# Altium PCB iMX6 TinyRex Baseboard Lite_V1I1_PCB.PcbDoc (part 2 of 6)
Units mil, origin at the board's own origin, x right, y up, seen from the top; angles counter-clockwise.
Board outline 3149.61 x 3543.31 mil, 6 copper layers (L1, L2, L3, L4 (PWR), L5, L6), stack 60.634 mil thick; 385 components, 309 nets, 1566 pads, 914 vias.
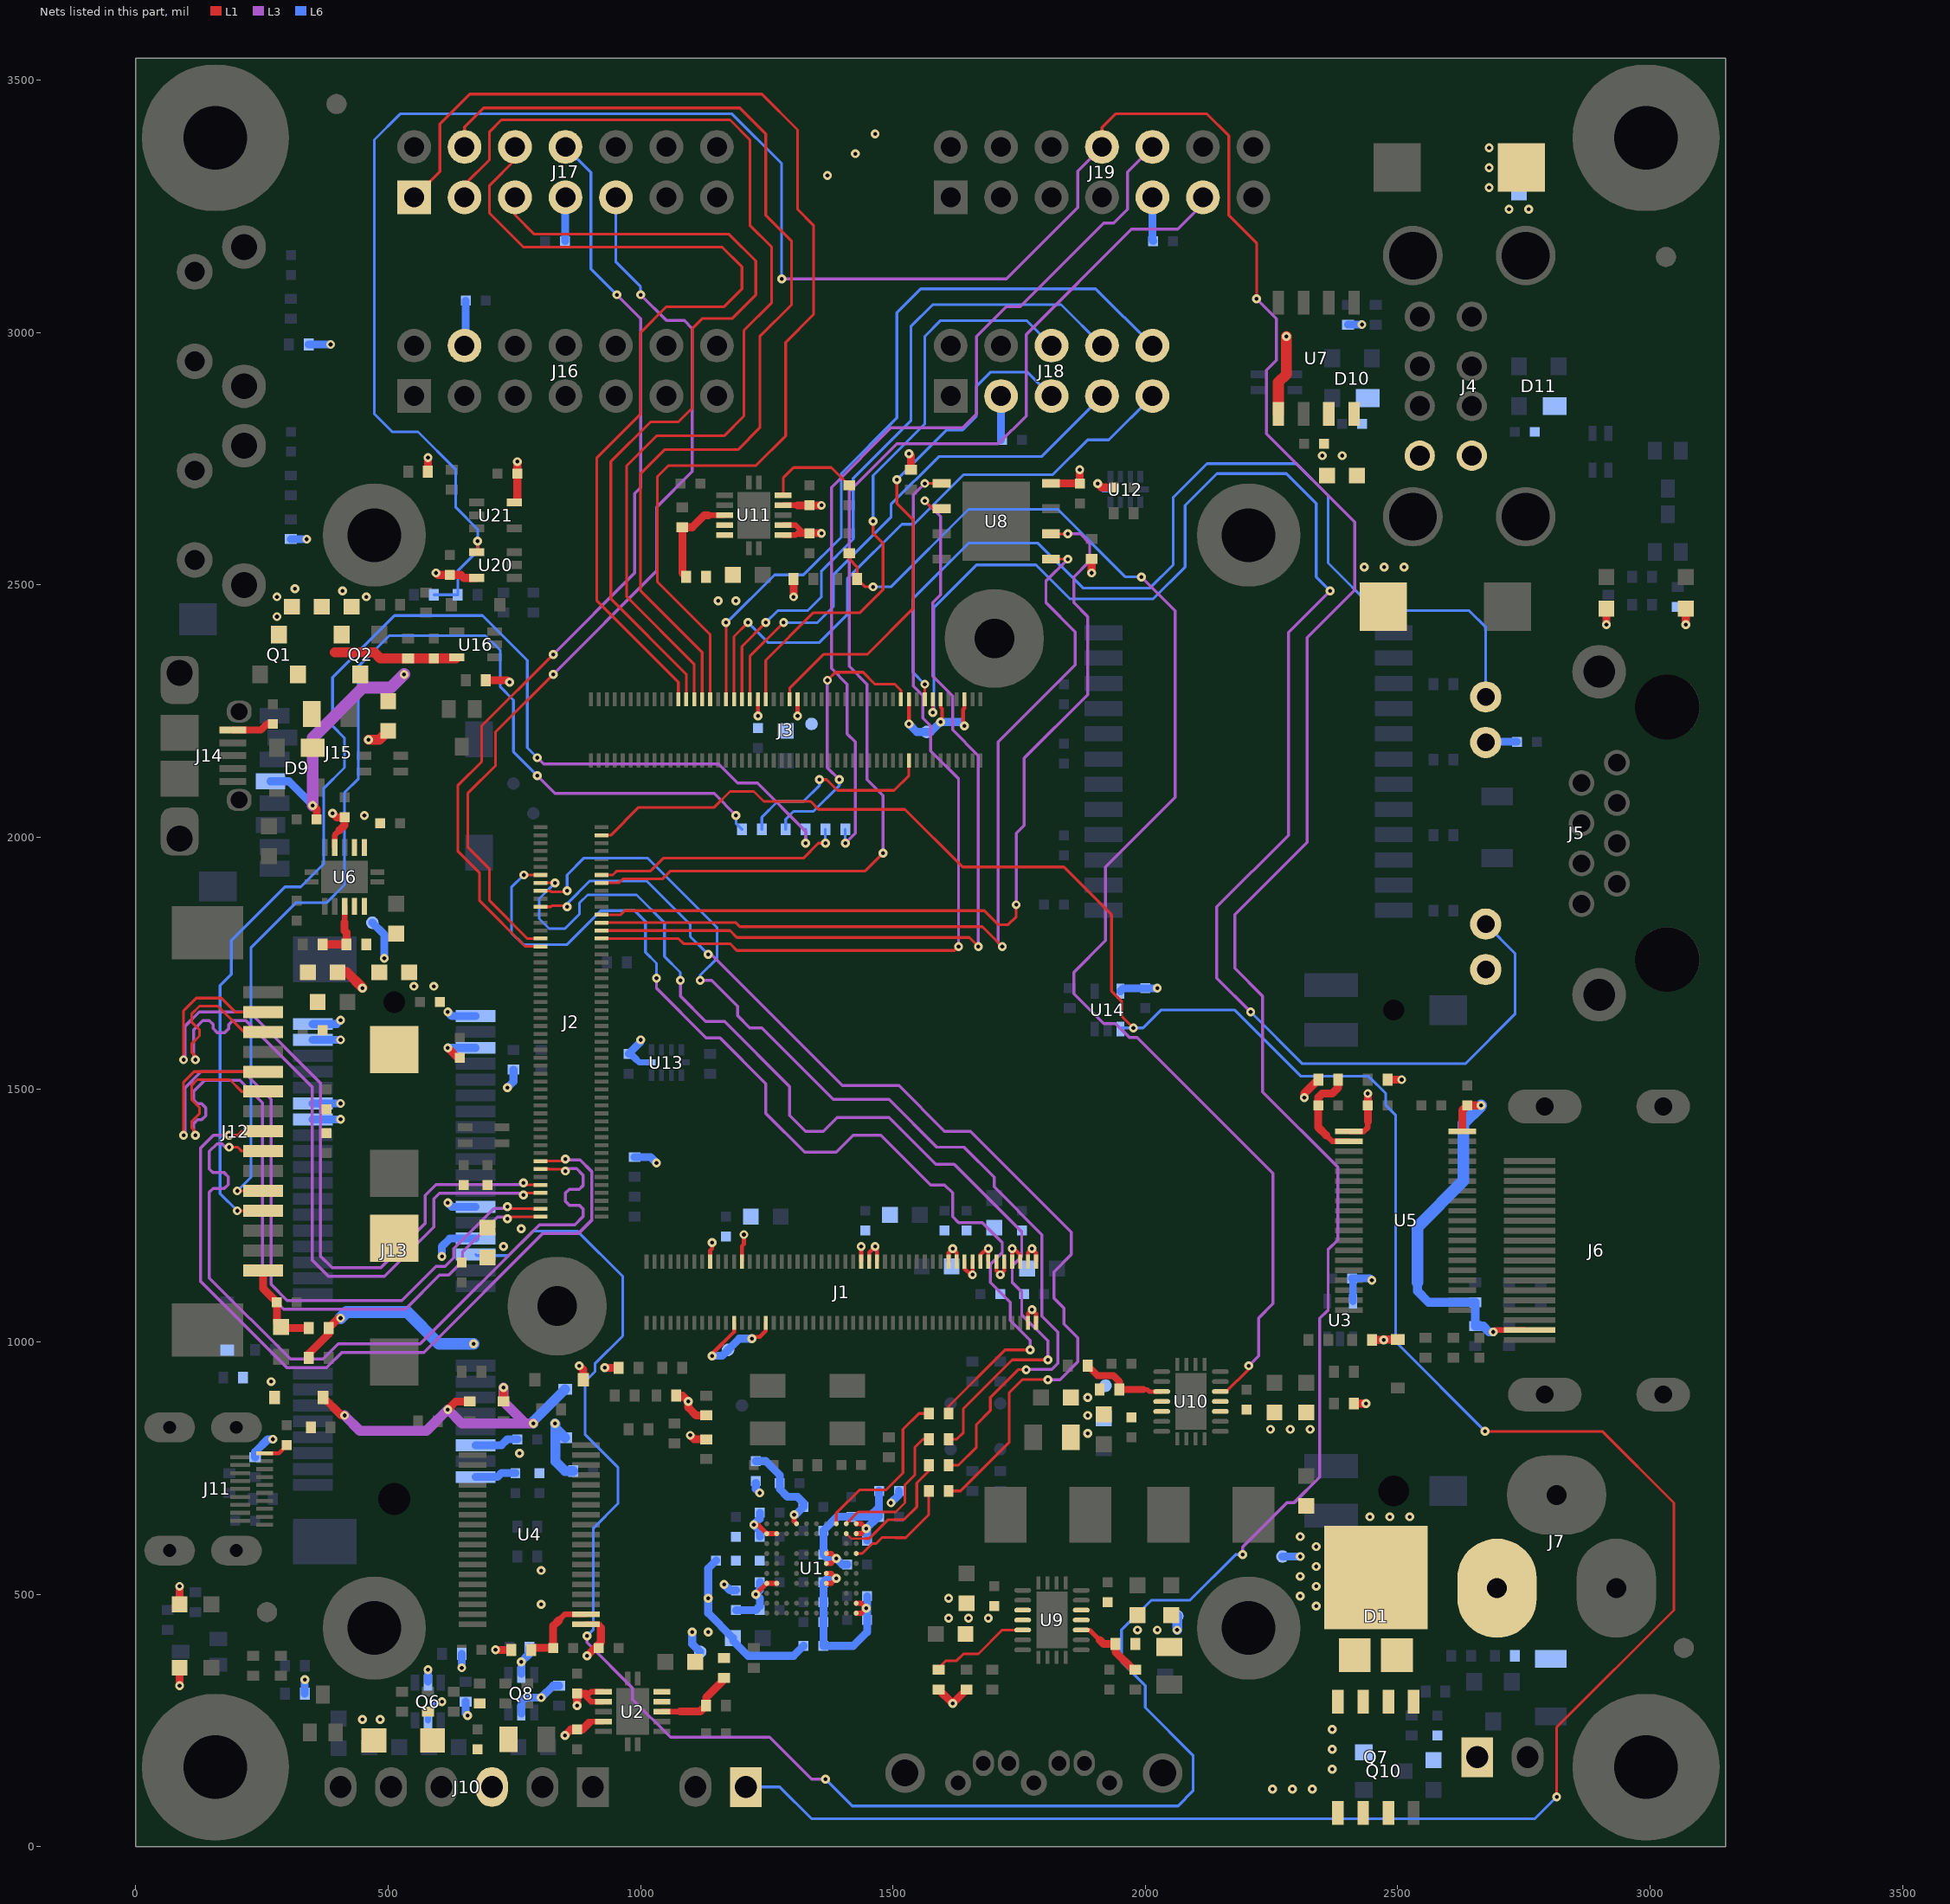
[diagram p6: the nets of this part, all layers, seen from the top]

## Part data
C1 C2 C3 C16 C29 C30 C37 C38 C61 C62 C63 C65 C66 C70 C231 C232 C381: library part C1608X5R0J226M080AC, "CAP CER 22UF 6.3V 20% X5R 0603"
C4 C5 C6 C7 C8 C9 C12 C13 C14 C15 C22 C23 C24 C25 C26 C27 C28 C32 C33 C34 C35 C36 C41 C42 C43 C44 C52 C53 C54 C55 C64 C69 C71 C72 C73 C74 C75 C76 C77 C79 C108 C114 C115 C116 C117 C118 C158 C160 C161 C165 C171 C176 C177 C187 C188 C190 C198 C200 C203 C230 C259 C260 C261 C265 C266 C267 C268: library part C1005X5R1H104K, "CAP CER .10UF 50V X5R 10% 0402"
C10 C20 C31 C58 C60 C91 C185: library part C1608X5R0J106M, "CAP CER 10UF 6.3V X5R 20% 0603"
C11 C17: library part JMK212BJ476MG-T, "CAP CER 47UF 6.3V 20% X5R 0805"
C18 C56 C89: library part C1005X5R1C105K, "CAP CER 1.0UF 16V X5R 0402"
C19 C57 C90 C262 C263 C264: library part C1005X5R1A475M, "CAP CER 4.7UF 10V 20% X5R 0402"
C21 C59 C92: library part GRM155R71H272KA01D, "CAP CER 2700PF 50V 10% X7R 0402"
C39 C40 C67 C68: library part C1005X5R1A225K, "CAP CER 2.2UF 10V 10% X5R 0402"
C45 C46 C47 C50 C51 C183 C184: library part C1005X7R1H221K, "CAP CER 220PF 50V X7R 10% 0402"
C48 C49: library part C1005C0G1H150J, "CAP CER 15PF 50V 5% NP0 0402"
C78: library part C2012X5R1C106M, "CAP CER 10UF 16V 20% X5R 0805"
C106: library part C2012X5R1C226K, "CAP CER 22UF 16V 10% X5R 0805"
C119: library part C1206X102KGRACTU, "CAP CER 1000PF 2000V X7R 1206 FT"
C156 C159: library part T495D337K010ATE150, "CAP TANT 330UF 10V 10% 2917"
C257 C258: library part T520D337M006ATE045, "CAP TANT 330UF 6.3V 20% 2917"
CR1: library part Card_Mini_PCIe, "Card MIni PCIe"
CR2: library part Card_Micro_SD, "Card Micro SD"
D1: "DIODE SCHOTTKY 40V 10A TO277A"
D2 D3 D6 D7 D16: "DIODE SCHOTTKY 30V 0.2A SOD323"
D4 D8 D12 D13 D19: "SUPPRESSOR ESD 24VDC 0603 SMD"
D5 D17 D18: library part "LS L29K-H1J2-1-Z", "LED SMARTLED RED 630NM 0603 SMD"
D9 D10 D11: "DIODE SWITCHING 50V SOT-143"
D14: library part "LG L29K-G2J1-24-Z", "LED SMARTLED GREEN 570NM 0603"
D15: "DIODE SCHOTTKY 40V 1A SOD123L"
D27: "DIODE SCHTKY 30MA 30V SOD-323"
FB1 FB2 FB24: library part MPZ1608S601A, "FERRITE CHIP BEAD 600 OHM SMD 1A"
FB3 FB4 FB5 FB8 FB11: "FERRITE CHIP 600 OHM 0402 420mA"
FB6 FB7 FB9 FB10 FB12: library part BLM18SG221TN1D, "FERRITE CHIP 220 OHM 2500MA 0603"
FID1 FID2 FID3 FID4 FID5 FID6 FID7 FID8: "Fiducial 40mil Diameter, 120mil Mask"
J1 J2 J3: library part DF40C-100DS-0.4V(51)_v1.1, "CONN RCPT 100POS 0.4MM SMD GOLD"
J4: library part 5787617-1_v1.1, "CONN RCPT R/A 4OVER4POS GOLD PCB"
J5: "CONN MOD JACK 8POS R/A G-Y PCB"
J6: library part 47151-0001_v1.1, "CONN RCPT 19POS HDMI RT ANG SMD"
J7: library part PJ-002AH_v1.1, "CONN PWR JACK 2.1X5.5MM HIGH CUR"
J8: "CONN HEADER 2POS .100 VERT GOLD"
J9: "CONN SATA HDR 7POS PCB VERT"
J10: library part 68001-206HLF, "CONN HEADER 6POS .100 STR 15AU"
J11: "CONN RCPT HDMI MICRO TYPE-D R/A"
J12: "CONN FPC BOTTOM 15POS 1.00MM R/A"
J13: "CONN MINI EXPRESS CARD 52POS SMD"
J14: library part 0475890001, "CONN RCPT MICRO USB AB R/A SMD"
J15: "CONN MICRO SD 8 POS SMD"
J16 J17 J19: library part D2514-6002-AR, "CONN HEADER 14POS VERT 10GOLD"
J18: library part D2510-6002-AR, "CONN HEADER 10POS VERT 10GOLD"
J20: "CONN MINI EXPRESS CARD LATCH SMD"
JP1: library part 68001-202HLF, "BERGSTIK II .100\" SR STRAIGHT"
L1 L2: library part IHLP2020CZER1R5M11, "FIXED IND 1.5UH 7.5A 18.5 MOHM"
L3 L4 L5 L6: "CHOKE COMM MODE 90 OHM .4A SMD"
M1: library part 3D_iMX6_TINYREX_MODULE_V1I1, "3D Model"
MH1 MH2 MH3 MH4: "Mounting Hole 7.4mm Diameter, 3.2mm Drill"
MH5 MH6: "Mounting Hole 5mm Diameter, 2mm Drill"
MH9 MH10 MH11 MH12: "Mounting Hole 5.2mm Diameter, 2.7mm Drill"
NUT3 NUT4: library part PFP1166, "ROEBUCK - PFP1166 - FULL NUT A4 SS M2 (PK 100)"
Q1 Q2: "MOSFET P-CH 20V 3.6A SOT-23"
Q3 Q4 Q5 Q9 Q11: "MOSFET N-CH 60V 310MA SOT323"
Q6 Q8: "MOSFET 2N-CH 60V 0.3A 6TSSOP"
Q7: "MOSFET P-CH 30V 8.8A 8-SOIC"
Q10: "TRANS PNP 40V 0.2A SOT23"
R1 R2 R3 R4 R10 R11 R23 R24 R26 R27 R28 R32 R33 R37 R44 R45 R52 R53 R64 R65 R81 R117 R140 R147 R201 R204 R206 R224 R247 R293: library part RC0402FR-0710KL, "RES 10.0K OHM 1/16W 1% 0402 SMD"
R5 R8 R9 R14 R15 R16 R22 R30 R31 R34 R39 R41 R46 R58 R59 R60 R61 R62 R63 R104 R105 R109 R135 R136 R138 R139 R153 R155 R162 R163 R164 R165 R174 R220 R304: library part RC0402JR-070RL, "RES 0.0 OHM 1/16W 0402 SMD"
R6 R7 R17 R19: library part RMCF0402FT4K99, "RES TF 4.99K OHM 1% 1/16W 0402"
R12 R13 R36 R40 R48 R49: library part RC0402FR-0747KL, "RES 47.0K OHM 1/16W 1% 0402 SMD"
R18: library part CRCW04022K10FKED, "RES 2.10K OHM 1/16W 1% 0402 SMD"
R20 R83 R226: library part CRCW04022K40FKED, "RES 2.40K OHM 1/16W 1% 0402 SMD"
R21 R50: library part RC0402FR-0727KL, "RES 27.0K OHM 1/16W 1% 0402 SMD"
R25 R29 R38 R214: library part RMCF0402FT100K, "RES 100K OHM 1/16W 1% 0402 SMD"
R35 R42 R43 R166 R167 R168 R169: library part RC0402FR-0722RL, "RES 22.0 OHM 1/16W 1% 0402 SMD"
R47: library part RC0402FR-0715KL, "RES 15.0K OHM 1/16W 1% 0402 SMD"
R51 R67: library part RC0402FR-071KL, "RES 1.00K OHM 1/16W 1% 0402 SMD"
R54 R55 R56 R57 R70 R71: library part RC0402FR-073K3L, "RES 3.30K OHM 1/16W 1% 0402 SMD"
R66 R141 R149: library part RMCF0402FT33R0, "RES TF 33 OHM 1% 1/16W 0402"
R68 R69 R144 R145 R146 R148: library part RMCF0402FT240R, "RES TF 240 OHM 1% 0.0625W 0402"
R72: library part CRCW0402390KFKED, "RES 390K OHM 1/16W 1% 0402 SMD"
R82: library part RC0402FR-073KL, "RES 3K OHM 1/16W 1% 0402 SMD"
R84 R85 R86 R87: library part RC0402FR-0775RL, "RES 75.0 OHM 1/16W 1% 0402 SMD"
R100: library part RNCP1206FTD1K00, "RES SMD 1K OHM 1% 1/2W 1206"
R211 R216: library part CRCW04021M02FKED, "RES 1.02M OHM 1/16W 1% 0402 SMD"
R213: library part CRCW0402113KFKED, "RES 113K OHM 1/16W 1% 0402 SMD"
R217: library part CRCW0402182KFKED, "RES 182K OHM 1/16W 1% 0402 SMD"
R225: library part RC0402FR-075K1L, "RES 5.10K OHM 1/16W 1% 0402 SMD"
R292: library part CRCW040211K8FKED, "RES 11.8K OHM 1/16W 1% 0402 SMD"
R296: library part CRCW040210K5FKED, "RES 10.5K OHM 1/16W 1% 0402 SMD"
R301: library part CRCW0402470KFKED, "RES 470K OHM 1/16W 1% 0402 SMD"
SCR3 SCR4: library part "MPMS 002 0008 PH", "MACHINE SCREW PAN PHILLIPS M2"
SPA3 SPA4: library part "SPACER 2.5/4.5X1.5MM", "SPACER 2.5/4.5X1.5MM"
SW1 SW2: "SWITCH TACTILE SPST-NO 0.05A 12V"
T1: "MODULE SINGLE GIGABIT LAN 24SOIC"
TP1 TP2 TP3 TP4 TP5 TP6 TP7 TP8 TP9 TP10 TP11 TP12 TP13 TP14 TP15: "Test Point 25mil"
U1: "IC RCVR HDMI 165MHZ LP 76-CSBGA"
U2 U6 U11: "IC REG LDO ADJ 1.5A 10SON"
U3: "IC BUFFER SCHMIT TRIG SC705"
U4: "IC HDMI RCVR PORT PROT 38-TSSOP"
U5: "IC HDMI TX PORT P/I 38-TSSOP"
U7: "IC SW DISTRIBUTION 2CHAN 8SOIC"
U8: library part SST25VF016B-75-4I-QAF, "IC FLASH 16MBIT 75MHZ 8WSON"
U9 U10: "IC REG BUCK BST SYNC ADJ 14VSON"
U12 U13: "IC USB SWITCH DUAL 1X2 10-QFN"
U14 U20 U21: "SINGLE POSITIVE AND GATE SC-70"
U16: "IC BUFF CMOS LVL/SFTR N-I SOT353"
U27: "IC VREF SHUNT ADJ SOT23-3"
Y1: library part ABM3B-28.63636MHZ-10-1-U-T, "CRYSTAL 28.63636MHZ 10PF SMD"

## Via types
v1: diameter 17.72, hole 7.87, L1 to L6, 471 vias
v2: diameter 17.72, hole 7.87, L1 to L6, tented both sides, 442 vias
v3: diameter 17.72, hole 7.87, L1 to L6, tented top, 1 vias

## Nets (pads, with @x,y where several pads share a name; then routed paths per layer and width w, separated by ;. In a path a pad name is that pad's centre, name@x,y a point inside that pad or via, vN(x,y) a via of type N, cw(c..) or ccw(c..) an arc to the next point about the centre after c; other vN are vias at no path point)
+1V2_TP: J3.6 J3.12 J3.20 TP7.1 | length 279.5
  L1 w6.69: v2(1594.49,2228.35) 1597.44,2231.3 1597.44,2254.16 1594.49,2257.11 J3.12@1594.49,2273.23
  L1 w7.87: v2(1531.5,2224.41) J3.20@1531.5,2273.23 ; v2(1641.73,2220.47) 1638.78,2223.43 1638.78,2252.95 1641.73,2255.9 J3.6@1641.73,2273.23
  L6 w15.75: v2(1531.5,2224.41) 1547.24,2208.66 TP7.1@1566.93,2208.66 1574.8,2208.66 v2(1594.49,2228.35) 1633.86,2228.35 v2(1641.73,2220.47)
+1V5: C20.1 FB10.2 R18.2 TP1.1 U6.9 U6.10 | length 80.7
  L6 w15.75: TP1.1@468.5,1830.71 492.13,1807.09 v1(492.13,1759.84)
+1V5_MPCIE: C259.1 C260.1 C261.1 C262.1 FB10.1 J13.6 J13.28 J13.48 | length 232.8
  L1 w15.75: v1(618.11,1582.68) 637.8,1562.99 C261.1@641.73,1562.99
  L6 w15.75: v1(618.11,1275.59) 625.98,1267.72 J13.28@673.23,1267.72 ; v1(618.11,1582.68) J13.48@673.23,1582.68 ; J13.6@673.23,795.28 724.41,795.28 736.22,807.09 C259.1@755.91,807.09
  other v1: 551.18,1704.72 590.55,1704.72
+1V8: C58.1 FB3.1 FB5.1 FB11.1 R82.2 TP4.1 U2.9 U2.10 | length 127.5
  L6 w15.75: v1(1102.36,425.2) 1102.36,401.57 TP4.1@1118.11,385.83 ; v1(1165.35,519.69) 1177.17,507.87 FB5.1@1188.98,507.87 ; FB11.1@1228.35,720.47 1228.35,708.66 v1(1236.22,700.79) ; v1(1496.06,681.1) 1511.81,696.85 FB3.1@1511.81,704.72
  other v1: 1133.86,425.2
+1V8_CVDD: C55.2 C177.2 FB5.2 U1.G1 U1.G2 | length 154.6
  L1 w9.84: v1(1228.35,500) U1.G1@1250,521.65 U1.G2@1269.69,521.65
  L6 w15.75: FB5.2@1188.98,468.5 1228.35,468.5 1236.22,476.38 1236.22,492.13 v1(1228.35,500) 1236.22,507.87 C177.2@1236.22,523.62
+1V8_DVDD: C41.2 C42.2 C43.2 C44.2 C45.1 C46.1 FB3.2 U1.A10 U1.B10 U1.D7 U1.E7 | length 438.5
  L1 w9.84: U1.E7@1368.11,561.02 1377.95,561.02 v1(1387.8,570.87) 1377.95,580.71 U1.D7@1368.11,580.71 ; U1.B10@1427.17,620.08 1437.01,620.08 v1(1446.85,629.92) 1437.01,639.76 U1.A10@1427.17,639.76
  L6 w15.75: C46.1@1409.45,559.06 1399.61,559.06 v1(1387.8,570.87) 1370.08,570.87 C43.2@1362.2,578.74 C42.2@1362.2,625.98 1389.76,653.54 C44.2@1417.32,653.54 1452.76,653.54 1472.44,673.23 ; C45.1@1448.82,606.3 1448.82,627.95 v1(1446.85,629.92) 1470.47,653.54 C41.2@1472.44,653.54 FB3.2@1472.44,704.72
+1V8_PVDD: C51.1 C190.2 FB11.2 U1.A4 | length 197.7
  L1 w9.84: v1(1304.13,657.48) 1304.13,644.68 U1.A4@1309.06,639.76
  L6 w15.75: FB11.2@1228.35,763.78 1248.03,763.78 1275.59,736.22 C190.2@1275.59,720.47 1275.59,708.66 1291.34,692.91 1311.02,692.91 1322.83,681.1 C51.1@1322.83,673.23 1307.09,657.48 v1(1304.13,657.48)
+2V5: C14.1 C91.1 C232.1 J3.48 J3.58 R224.2 R225.2 TP15.1 U11.9 U11.10 | length 101.6
  L1 w7.87: v2(1232.28,2240.16) J3.58@1232.28,2273.23 ; v2(1311.02,2240.16) J3.48@1311.02,2273.23
  L1 w15.75: v2(1303.15,2476.38) R224.2@1303.15,2511.81
  other v2: 1153.54,2468.5 1188.98,2468.5
+3V0_ALWAYS_TP: J1.69 J1.77 TP8.1 | length 226
  L1 w7.87: v2(1141.73,972.44) 1141.73,976.38 1185.04,1019.69 J1.77@1185.04,1037.8 ; v2(1220.47,1006.44) 1223.66,1009.63 1235.75,1009.63 1248.03,1021.91 J1.69@1248.03,1037.8
  L6 w15.75: v2(1141.73,972.44) 1161.42,972.44 TP8.1@1173.23,984.25 1195.42,1006.44 v2(1220.47,1006.44)
+3V3: C9.2 C12.1 C13.1 C17.1 C27.2 C28.2 C29.1 C30.1 C34.1 C35.1 C36.1 C68.1 C70.1 C75.2 C76.2 C115.1 C158.1 C171.1 C176.1 C185.1 C203.1 C231.1 D3.2 D5.2 D7.2 D14.2 D15.2 D17.2 D18.2 FB4.2 FB8.2 FB9.1 J1.22 J1.24 J1.42 J1.44 J1.46 J5.10 J5.12 J15.4 J16.4 J17.7 J18.3 J19.9 Q6.2 Q6.5 Q8.2 Q8.5 R6.2 R7.2 R10.2 R11.2 R12.2 R13.2 R32.2 R33.2 R36.2 R37.2 R46.2 R54.2 R56.2 R65.2 R70.2 R71.2 R81.2 R117.2 R138.1 R140.2 R147.2 R201.2 R204.1 R206.2 R216.2 TP13.1 U3.5 U8.8 U10.4 U10.5 U12.10 U13.10 U14.5 U20.5 U21.5 | length 3479.3
  L1 w7.87: J1.46@1437.01,1159.06 v2(1437.01,1188.98) ; J1.44@1452.76,1159.06 1452.76,1177.17 v2(1464.57,1188.98) 1468.5,1185.04 J1.42@1468.5,1159.06 ; J1.24@1610.24,1159.06 1610.24,1177.17 v2(1618.11,1185.04) 1625.98,1177.17 J1.22@1625.98,1159.06
  L1 w15.75: v1(86.61,318.9) D5.2@86.61,354.33 ; D14.2@86.61,480.31 v1(86.61,515.75) ; R37.2@342.52,968.5 342.52,976.38 381.89,1015.75 R138.1@381.89,1027.56 401.57,1047.24 v1(405.51,1047.24) ; v1(350.39,2062.99) 358.27,2055.12 C158.1@358.27,2035.43 ; R117.2@578.74,2724.41 v1(578.74,2751.97) ; v1(594.49,2523.62) 598.43,2519.69 C171.1@622.05,2519.69 643.7,2519.69 649.61,2513.78 U20.5@675.2,2513.78 U20.5@671.26,2513.78 ; R201.2@692.91,2311.02 736.22,2311.02 v1(740.16,2307.09) ; v1(712.6,389.76) R11.2@744.09,389.76 ; U21.5@750,2663.39 755.91,2669.29 v1(755.91,2744.09) ; v1(878.71,952.76) 886.58,944.88 D7.2@886.58,925.2 ; v1(929.13,948.82) R12.2@956.69,948.82 ; R13.2@1070.87,893.7 1082.68,893.7 v1(1094.49,881.89) 1094.49,870.08 1110.24,854.33 R6.2@1129.92,854.33 ; v1(1098.43,814.96) 1106.3,807.09 R7.2@1129.92,807.09 ; v1(1531.5,2759.84) 1535.43,2755.91 R206.2@1535.43,2728.35 ; U8.8@1812.99,2700.98 1869.88,2700.98 C203.1@1870.08,2700.79 v2(1870.08,2728.35) ; v1(1893.7,2523.62) R204.1@1893.7,2551.18 ; v2(1905.51,2700.79) 1913.39,2692.91 C9.2@1937.01,2692.91 ; v2(2314.96,1484.25) 2314.96,1492.13 R46.2@2342.52,1519.69 ; R36.2@2448.82,1003.94 v2(2472.44,1003.94) 2473.2,1004.69 D3.2@2500,1004.69 ; v1(2913.39,2421.26) D17.2@2913.39,2452.76 ; v1(3070.87,2421.26) D18.2@3070.87,2452.76
  L3 w23.62: v1(350.39,2062.99) 350.39,2196.85 449.8,2296.26 504.92,2296.26 v1(531.5,2322.83)
  L6 w11.81: Q6.2@578.74,250 578.74,267.72 596.06,285.04 603.94,285.04 v1(606.3,287.4) ; 992.13,1559.06 997.51,1553.67 U13.10@1017.32,1553.67 ; v2(1905.51,2700.79) 1917.32,2688.98 U12.10@1926.77,2688.98
  L6 w13.78: C75.2@976.38,1570.87 980.31,1570.87 992.13,1559.06
  L6 w14.96: C35.1@2409.45,1125.98 2411.42,1124.02 U3.5@2411.42,1080.71
  L6 w15.75: J15.4@266.73,2110.83 303.08,2110.83 350.39,2063.51 v1(350.39,2062.99) ; R147.2@307.09,2590.55 v1(338.58,2590.55) ; R81.2@334.65,303.15 v1(334.65,330.71) ; R140.2@342.52,2976.38 v1(385.83,2976.38) ; Q6.5@578.74,326.77 v1(578.74,350.39) ; v1(645.67,354.33) R70.2@645.67,381.89 ; J16.4@651.18,2974.02 653.54,2976.38 C36.1@653.54,3062.99 ; R56.2@653.54,287.4 653.54,263.78 v1(657.48,259.84) ; v2(736.22,1503.94) 748.03,1515.75 R65.2@748.03,1539.37 ; Q8.2@763.78,263.78 763.78,287.4 771.65,295.28 v1(803.15,295.28) 826.77,318.9 R54.2@838.58,318.9 ; Q8.5@763.78,342.52 v1(763.78,366.14) 779.53,381.89 R71.2@779.53,393.7 ; C28.2@850.39,3181.1 850.39,3266.14 J17.7@851.97,3267.72 ; C75.2@976.38,1570.87 1000,1594.49 v2(1000,1598.43) ; R10.2@988.19,1366.14 1019.69,1366.14 v2(1031.5,1354.33) ; FB8.2@1149.61,566.93 1133.86,551.18 v1(1133.86,492.13) 1133.86,462.6 C185.1@1183.07,413.39 1183.07,408 1213.12,377.95 1303.15,377.95 FB4.2@1322.83,397.64 ; C34.1@1714.17,2787.4 J18.3@1714.17,2874.02 ; U14.5@1950.79,1694.88 1956.69,1700.79 C76.2@2000,1700.79 v2(2023.62,1700.79) ; J19.9@2014.17,3267.72 2014.17,3182.68 C27.2@2015.75,3181.1 ; R32.2@2401.57,3015.75 v1(2429.13,3015.75) ; C35.1@2409.45,1125.98 2444.88,1125.98 v2(2448.82,1122.05) ; J5.10@2675.59,2188.98 C115.1@2736.22,2188.98
  L6 w23.62: v1(405.51,1047.24) 417.32,1059.06 537.58,1059.06 600.57,996.06 v1(669.29,996.06)
  other v1: 448.82,251.97 484.25,251.97 803.15,480.31 803.15,547.24 728.35,1188.98 763.78,1224.41
  other v2: 1885.83,818.9 1885.83,854.33 1885.83,889.76
+3V3_DVDDIO: C47.1 C50.1 C52.2 C53.2 C54.2 FB4.1 U1.F7 U1.G7 U1.J10 U1.K10 | length 420.4
  L1 w9.84: U1.G7@1368.11,521.65 1377.95,521.65 v1(1387.8,531.5) 1377.95,541.34 U1.F7@1368.11,541.34 ; U1.K10@1427.17,462.6 1437.01,462.6 v1(1446.85,472.44) 1437.01,482.28 U1.J10@1427.17,482.28
  L6 w15.75: v1(1387.8,531.5) 1370.08,531.5 C50.1@1362.2,523.62 C54.2@1362.2,444.88 FB4.1@1362.2,397.64 1421.26,397.64 1448.82,425.2 C52.2@1448.82,448.82 1448.82,470.47 v1(1446.85,472.44) 1448.82,474.41 C47.1@1448.82,496.06
+3V3_HDMI_IN: C72.1 R11.1 U4.2 | length 163
  L1 w11.02: 838.58,448.82 850.39,460.63 U4.2@891.73,460.63
  L1 w15.75: R11.1@783.46,389.76 787.4,393.7 C72.1@826.77,393.7 826.77,437.01 838.58,448.82
+3V3_HDMI_OUT: C23.1 R46.1 U5.2 | length 194.8
  L1 w11.02: 2358.27,1409.45 2370.08,1397.64 U5.2@2403.54,1397.64
  L1 w15.75: 2358.27,1409.45 2342.52,1425.2 C23.1@2342.52,1468.5 2342.52,1484.25 2350.39,1492.13 2370.08,1492.13 2381.89,1503.94 R46.1@2381.89,1519.69
+3V3_MPCIE: C257.1 C258.1 C263.1 C264.1 C265.1 C266.1 C267.1 C268.1 FB9.2 J13.2 J13.24 J13.39 J13.41 J13.52 | length 343.8
  L6 w15.75: J13.39@350.39,1440.95 v1(405.51,1440.95) ; J13.41@350.39,1472.44 v1(405.51,1472.44) ; v1(606.3,1169.29) 606.3,1188.98 622.05,1204.72 J13.24@673.23,1204.72 ; v1(618.11,1653.54) 625.98,1645.67 J13.52@673.23,1645.67 ; J13.2@673.23,732.28 716.54,732.28 724.41,740.16 C265.1@751.97,740.16
  other v1: 759.84,779.53
+3V3_TVDD: C183.1 C184.1 C187.2 C188.2 FB8.1 U1.B1 U1.B2 | length 109.6
  L1 w9.84: v1(1224.41,637.8) 1232.28,637.8 U1.B1@1250,620.08 U1.B2@1269.69,620.08
  L6 w15.75: C183.1@1236.22,614.17 1236.22,625.98 v1(1224.41,637.8) 1236.22,649.61 C184.1@1236.22,661.42
+5V: C11.1 C15.1 C16.1 C22.1 C40.1 C61.1 C62.1 C63.1 C71.1 C165.1 D6.2 FB1.1 FB2.1 FB6.1 FB7.1 FB24.1 J1.76 J1.84 R26.2 R104.1 R211.2 TP12.1 U4.1 U5.1 U7.7 U9.4 U9.5 | length 612.3
  L1 w7.87: J1.84@1137.8,1159.06 1137.8,1181.1 1141.73,1185.04 v2(1141.73,1196.85) ; J1.76@1200.79,1159.06 1200.79,1189.76 1204.72,1193.7 v2(1204.72,1212.6)
  L1 w11.02: U4.1@891.73,440.95 917.32,440.95 921.26,437.01 921.26,433.07 ; U5.1@2403.54,1417.32 2433.07,1417.32 2440.94,1425.2 2440.94,1437.01
  L1 w15.75: v1(893.7,377.95) 921.26,405.51 921.26,433.07 ; 2440.94,1437.01 C22.1@2440.94,1468.5 v2(2440.94,1492.13) ; R26.2@2480.31,1519.69 v2(2507.87,1519.69)
  L1 w19.68: FB7.1@399.61,1732.28 418.31,1732.28 v1@448.82,1701.77 ; v1(460.63,2192.91) 482.28,2192.91 FB24.1@500,2210.63
  L6 w19.68: v3(830.71,838.58) 831.69,837.6 831.69,828.97 ; D6.2@850.39,810.27 831.69,828.97 ; R104.1@866.14,744.09 850.39,744.09 831.69,762.8 831.69,828.97 ; v1(2062.99,429.13) TP12.1@2062.99,456.69
  other v1: 1984.25,429.13 2023.62,429.13 448.82,1700.79
  other v2: 456.69,2476.38 409.45,2488.19 2350.39,2755.91 2389.76,2755.91 2720.47,3244.09 2759.84,3244.09
+5V_FTDI: C77.1 C78.1 D15.1 J10.3 R55.2 R57.2
+5V_HDMI_IN_CON: C74.1 D2.2 D16.2 J11.19 R38.2 R40.2 R174.1 | length 106.9
  L1 w7.87: J11.19@254.92,779.53 283.46,779.53 C74.1@299.21,795.28
  L6 w15.75: R40.2@236.22,771.65 236.22,781.86 261.44,807.09 v1(271.65,807.09)
  other v1: 267.72,921.26
+5V_HDMI_IN_I2C: D2.1 D6.1 R48.2 R49.2 | length 732.8
  L1 w15.75: D2.1@370.83,889.76 371.85,889.76 407.28,854.33 v1(413.39,854.33) ; v1(618.11,866.14) 633.86,881.89 R48.2@661.42,881.89 ; R49.2@728.35,881.89 v1(728.35,909.45)
  L3 w19.68: v1(413.39,854.33) 443.9,823.82 575.79,823.82 v1(618.11,866.14) 645.67,838.58 771.65,838.58 ; v1(728.35,909.45) 728.35,881.89 771.65,838.58 ; v1(787.4,838.58) 771.65,838.58
  L6 w19.68: v1(787.4,838.58) 787.4,843.28 D6.1@850.39,906.27
+5V_HDMI_OUT_CON: C25.1 J6.18 R17.2 R19.2 U5.38 | length 778.4
  L1 w11.02: U5.38@2627.95,1417.32 2627.95,1425.2
  L1 w11.81: v1(2688.98,1019.68) 2692.91,1023.62 J6.18@2751.97,1023.62
  L1 w15.75: 2627.95,1425.2 2627.95,1458.66 C25.1@2637.8,1468.5 v2(2665.35,1468.5)
  L6 w17.72: 2539.37,1118.11 2539.37,1100.45 2561.08,1078.74 R19.2@2653.54,1078.74 R17.2@2653.54,1031.5 2669.29,1031.5 2681.1,1019.68 v1(2688.98,1019.68)
  L6 w23.62: 2539.37,1118.11 2539.37,1228.35 2629.92,1318.9 2629.92,1433.07 v2(2665.35,1468.5)
+5V_MPCIE: C60.1 C69.1 FB7.2 J13.49 J13.51 | length 113.5
  L6 w15.75: J13.49@350.39,1598.43 v1(405.51,1598.43) ; J13.51@350.39,1629.92 397.64,1629.92 v1(405.51,1637.8)
+5V_USB0_VBUS: C156.1 C160.1 D10.1 FB1.2 J4.5 U7.8
  other v2: 2433.86,2535.43 2473.23,2535.43 2512.6,2535.43
+5V_USB1_VBUS: C159.1 C161.1 D11.1 FB2.2 J4.1 U7.5 | length 160.1
  L1 w21.65: U7.5@2263.58,2838.58 2263.58,2901.38 2279.53,2917.32 v2(2279.53,2992.13)
  other v2: 2681.1,3287.4 2681.1,3326.77 2681.1,3366.14
+5V_USB_OTG: C26.1 C106.1 D9.1 FB24.2 J14.1 Q2.3 | length 72.8
  L1 w13.78: J14.1@191.93,2212.6 248.03,2212.6 259.84,2224.41
+5V_USB_OTG_B: FB6.2 FB12.2 Q1.3
+5V_USB_OTG_Q: C230.2 Q1.2 Q2.2 R214.2 U16.5 | length 245
  L1 w19.68: 393.7,2366.14 472.44,2366.14 484.25,2354.33 R214.2@539.37,2354.33 C230.2@590.55,2354.33 U16.5@633.86,2354.33
+V_INPUT: C10.1 C79.1 J7.1 J8.1 Q7.1 Q7.2 Q7.3 Q10.2 R100.2 R292.2
  other v1: 2251.97,114.17 2291.34,114.17 2330.71,114.17 2370.08,153.54 2370.08,192.91 2370.08,232.28
+VCC_MIPI_CSI: C31.1 C32.1 J12.15 R138.2 | length 182.8
  L1 w15.75: J12.15@251.97,1141.73 251.97,1106.3 C32.1@279.53,1078.74 279.53,1037.4 C31.1@287.4,1029.53 289.37,1027.56 R138.2@342.52,1027.56
+VIN: C1.1 C2.1 C3.1 C4.1 C5.1 C6.1 C7.1 C18.1 C19.1 C37.1 C38.1 C39.1 C56.1 C57.1 C65.1 C66.1 C67.1 C89.1 C90.1 C381.1 D1.3 FB12.1 J1.1 J1.2 J1.3 J1.4 J1.6 J1.8 J1.10 J1.12 J1.14 J1.16 J1.18 J1.20 R24.2 R27.2 R28.2 TP9.1 U2.1 U2.2 U2.4 U6.1 U6.2 U6.4 U9.10 U9.11 U10.10 U10.11 U11.1 U11.2 U11.4 | length 983.9
  L1 w7.87: J1.20@1641.73,1159.06 1641.73,1145.67 1654.33,1133.07 v2(1657.48,1133.07) ; v2@1657.48,1133.86 J1.18@1657.48,1159.06 ; J1.16@1673.23,1159.06 1673.23,1172.44 1685.83,1185.04 v2(1688.98,1185.04) ; J1.14@1688.98,1159.06 v2@1688.98,1184.25 ; J1.12@1704.72,1159.06 1704.72,1140.95 v2(1712.6,1133.07) 1720.47,1140.94 J1.10@1720.47,1159.06 ; J1.8@1736.22,1159.06 v2@1736.22,1184.25 ; v2(1736.22,1185.04) 1739.37,1185.04 1751.97,1172.44 J1.6@1751.97,1159.06 ; J1.3@1767.72,1037.8 1767.72,1055.91 v2(1775.59,1063.78) 1783.46,1055.91 J1.1@1783.46,1037.8 ; J1.4@1767.72,1159.06 1767.72,1177.17 v2(1775.59,1185.04) 1783.46,1177.17 J1.2@1783.46,1159.06
  L1 w11.02: U6.4@393.7,1979.33 393.7,2003.94 403.54,2013.78 ; 891.73,297.24 901.57,307.09 U2.1@926.18,307.09 ; 893.7,295.28 901.57,287.4 U2.2@926.18,287.4 ; 897.64,248.03 U2.4@926.18,248.03 ; U11.1@1282.48,2598.43 1307.09,2598.43 1314.96,2606.3 ; U11.2@1282.48,2618.11 1307.09,2618.11 1318.9,2606.3 ; U11.4@1282.48,2657.48 1311.02,2657.48
  L1 w15.75: v1(389.76,2047.24) 397.64,2039.37 C19.1@413.39,2039.37 413.39,2023.62 403.54,2013.78 ; v1(850.39,220.47) 862.2,232.28 C57.1@874.02,232.28 884.84,232.28 897.64,245.08 ; v1(874.02,279.53) C56.1@874.02,303.15 891.73,303.15 ; 1311.02,2657.48 C90.1@1334.65,2657.48 v2(1358.27,2657.48) ; 1314.96,2602.36 C89.1@1334.65,2602.36 v2(1358.27,2602.36) ; R27.2@1590.55,311.02 v1(1618.11,283.46) R24.2@1645.67,311.02 ; R28.2@2413.39,877.95 v2(2437.01,877.95)
  L6 w15.75: TP9.1@2271.65,574.8 v1(2307.09,574.8)
  other v1: 1610.24,452.76 1649.61,452.76 1688.98,452.76 2338.58,476.38 1610.24,492.13 2307.09,496.06 2338.58,515.75 2307.09,535.43 2338.58,555.12 2338.58,594.49 2307.09,614.17 2444.88,653.54 2484.25,653.54 2523.62,653.54 452.76,2043.31 1370.08,3311.02 1425.2,3354.33 1464.57,3393.7
  other v2: 2248.03,826.77 2287.4,826.77 2326.77,826.77 279.53,2437.01 279.53,2476.38 314.96,2492.13
+VIN_D: D1.1 D1.2 Q7.5 Q7.6 Q7.7 Q7.8
AUD4_CLK: J2.14 R167.2 | length 2071
  L1 w5.4: v2(768.5,1925.2) J2.14@801.57,1925.2 ; R167.2@1610.24,858.27 1610.24,872.3 1722.18,984.25 v2(1771.65,984.25)
  L3 w5.9: v2(1031.5,1720.47) 1031.5,1700.79 1129.92,1602.36 1157.48,1602.36 1248.03,1511.81 1248.03,1452.76 1324.8,1375.98 1387.8,1375.98 1421.26,1409.45 1476.38,1409.45 1574.8,1311.02 1602.36,1311.02 1618.11,1295.28 1618.11,1248.03 1629.92,1236.22 1677.17,1236.22 1716.54,1196.85 1716.54,1177.17 1692.91,1153.54 1692.91,1118.11 1732.28,1078.74 1732.28,1042.47 1771.65,1003.1 v2(1771.65,984.25)
  L6 w5.4: v2(768.5,1925.2) 744.09,1900.79 744.09,1811.02 767.72,1787.4 854.33,1787.4 921.26,1854.33 988.19,1854.33 1009.65,1832.87 1009.65,1772.11 1031.5,1750.26 v2(1031.5,1720.47)
AUD4_CLK_R: R167.1 U1.A8 | length 336.7
  L1 w5.4: U1.A8@1387.8,639.76 1387.8,660.88 1433.8,706.89 1486.42,706.89 1519.69,740.16 1519.69,826.77 1551.18,858.27 R167.1@1570.87,858.27
AUD4_RXD: J2.22 R169.2 | length 2090.9
  L1 w5.4: J2.22@801.57,1862.2 821.91,1862.2 824.08,1864.37 852.17,1864.37 v2(854.33,1862.2) ; R169.2@1610.24,704.72 1633.86,704.72 1730.51,801.38 1730.51,899.8 1755.91,925.2 v2(1807.09,925.2)
  L3 w5.9: v2(1133.86,1767.72) 1140.02,1767.72 1399.86,1507.87 1511.81,1507.87 1602.36,1417.32 1653.54,1417.32 1853.54,1217.32 1853.54,1173.27 1818.9,1138.63 1818.9,1086.61 1838.58,1066.93 1838.58,1035.43 1866.14,1007.87 1866.14,960.63 1830.71,925.2 v2(1807.09,925.2)
  L6 w5.4: v2(854.33,1862.2) 854.33,1868.37 899.35,1913.39 1011.81,1913.39 1098.43,1826.77 1098.43,1803.15 v2(1133.86,1767.72)
AUD4_RXD_R: R169.1 U1.D10 | length 223.1
  L1 w5.4: U1.D10@1427.17,580.71 1438.98,580.71 1458.66,600.39 1466.54,600.39 1478.54,612.4 1503.48,612.4 1503.88,612.01 1525.39,612.01 1570.87,657.48 R169.1@1570.87,704.72
AUD4_TXC: J2.16 R166.2 | length 2098
  L1 w5.4: J2.16@801.57,1909.45 v2(830.71,1909.45) ; R166.2@1610.24,807.09 1625.98,807.09 1639.57,820.67 1639.57,867.91 1736.22,964.57 v2(1807.09,964.57)
  L3 w5.9: v2(1078.74,1716.54) 1078.74,1685.04 1128.89,1634.89 1166.27,1634.89 1295.28,1505.88 1295.28,1448.82 1326.77,1417.32 1362.2,1417.32 1389.76,1444.88 1492.13,1444.88 1585.04,1351.97 1621.31,1351.97 1755.12,1218.16 1755.12,1169.29 1736.22,1150.39 1736.22,1118.11 1755.12,1099.21 1755.12,1053.96 1807.09,1001.99 v2(1807.09,964.57)
  L6 w5.4: v2(830.71,1909.45) 799.21,1877.95 799.21,1838.58 818.9,1818.9 850.39,1818.9 878.94,1847.44 878.94,1869.62 895.14,1885.83 992.13,1885.83 1047.24,1830.71 1047.24,1763.78 1078.74,1732.28 v2(1078.74,1716.54)
AUD4_TXC_R: R166.1 U1.A9 | length 285.7
  L1 w5.4: U1.A9@1407.48,639.76 1430.91,663.19 1505.71,663.19 1523.62,681.1 1523.62,716.54 1543.31,736.22 1543.31,791.34 1559.06,807.09 R166.1@1570.87,807.09
AUD4_TXFS: J2.18 R168.2 | length 2090.4
  L1 w5.4: J2.18@801.57,1893.7 821.12,1893.7 823.29,1891.54 852.17,1891.54 v2(854.33,1893.7) ; R168.2@1610.24,755.91 1629.92,755.91 1665.35,791.34 1665.35,836.36 1692.91,863.92 1692.91,889.76 1748.03,944.88 v2(1763.78,944.88)
  L3 w5.9: v2(1118.11,1716.54) 1140.9,1716.54 1192.13,1665.31 1192.13,1646.46 1216.54,1622.05 1240.16,1622.05 1381.89,1480.31 1492.13,1480.31 1586.61,1385.83 1640.9,1385.83 1700.79,1325.94 1700.79,1307.09 1795.28,1212.6 1795.28,1051.18 1826.77,1019.68 1826.77,957.53 1814.91,945.67 1764.57,945.67 v2(1763.78,944.88)
  L6 w5.4: v2(854.33,1893.7) 854.33,1925.2 887.99,1958.86 1013.58,1958.86 1151.77,1820.67 1151.77,1760.3 1118.11,1726.64 v2(1118.11,1716.54)
AUD4_TXFS_R: R168.1 U1.B9 | length 262.4
  L1 w3.94: U1.B9@1407.48,620.08 1417.32,610.24 1444.88,610.24
  L1 w5.4: 1444.88,610.24 1452.76,610.24 1490.35,647.83 1521.85,647.83 1547.24,673.23 1547.24,720.47 1570.87,744.09 R168.1@1570.87,755.91
BOOT_MODE0_CON: J2.3 JP1.1 U14.1 | length 5511.9
  L1 w5.4: J2.3@922.83,2003.94 940.94,2003.94 996.06,2059.06 1145.67,2059.06 1177.17,2090.55 1224.41,2090.55 1244.09,2070.87 1336.87,2070.87 1352.62,2055.12 1523.62,2055.12 1637.8,1940.94 1838.58,1940.94 1933.07,1846.46 1933.07,1695.14 1952.76,1675.45 1952.76,1645.67 v2(1976.38,1622.05) ; v1(2673.23,822.83) 2905.51,822.83 3047.24,681.1 3047.24,468.5 2814.96,236.22 v1(2814.96,98.43)
  L6 w5.4: JP1.1@1208.66,118.11 1275.59,118.11 1338.58,55.12 2771.65,55.12 v1(2814.96,98.43) ; U14.1@1950.79,1620.08 1952.76,1622.05 v2(1976.38,1622.05) 1995.46,1622.05 2030.9,1657.48 2177.17,1657.48 2308.46,1526.18 2442.32,1526.18 2476.38,1492.13 2476.38,1468.5 2496.06,1448.82 2496.06,1000 v1(2673.23,822.83)
BUF_SYS_RSTN: J13.22 J19.8 R64.2 R155.2 U20.4 | length 9703.2
  L1 w5.4: U20.4@671.26,2564.96 677.17,2570.87 v1(677.17,2586.61) ; J19.8@1914.17,3367.72 1914.17,3406.3 1940.95,3433.07 2122.05,3433.07 2165.35,3389.76 2165.35,3232.28 2220.47,3177.17 v1(2220.47,3066.93)
  L3 w5.9: v1(893.7,417.32) 893.7,404.68 984.25,314.13 984.25,291.34 1059.06,216.54 1255.91,216.54 1338.58,133.86 v1(1366.14,133.86) ; v1(1279.53,3106.3) 1724.41,3106.3 1866.14,3248.03 1866.14,3319.69 J19.8@1914.17,3367.72 ; v1(2192.91,578.74) 2192.91,593.65 2281.15,681.89 2295.23,681.89 2345.67,732.33 2345.67,1046.46 2362.2,1062.99 2362.2,1182.8 2381.1,1201.7 2381.1,1346.41 2232.28,1495.23 2232.28,1685.04 2177.17,1740.16 2177.17,1846.46 2320.87,1990.16 2320.87,2395.67 2414.96,2489.76 2414.96,2624.41 2240.16,2799.21 2240.16,2925.2 2259.84,2944.88 2259.84,3027.56 v1(2220.47,3066.93)
  L6 w5.4: R64.2@590.55,2480.31 R155.2@637.8,2480.31 637.8,2527.56 677.17,2566.93 v1(677.17,2586.61) 677.17,2610.24 633.86,2653.54 633.86,2728.35 559.06,2803.15 507.87,2803.15 472.44,2838.58 472.44,3381.89 523.62,3433.07 1181.1,3433.07 1279.53,3334.65 v1(1279.53,3106.3) ; J13.22@673.23,1173.23 675.39,1171.06 738.32,1171.06 786.54,1219.27 875.21,1219.27 964.57,1129.92 964.57,1011.81 909.45,956.69 909.45,940.94 889.76,921.26 889.76,816.67 954.92,751.51 954.92,679.33 906.5,630.91 906.5,430.12 v1(893.7,417.32) ; v1(1366.14,133.86) 1419.49,80.51 2064.76,80.51 2094.49,110.24 2094.49,181.1 2000,275.59 2000,318.9 1952.76,366.14 1952.76,429.13 2011.81,488.19 2088.33,488.19 2178.88,578.74 v1(2192.91,578.74)
CPU_GPIO0: J19.10 R43.2 | length 1809
  L3 w5.9: v2(1405.51,1988.19) 1425.2,2007.87 1425.2,2188.98 1409.45,2204.72 1409.45,2303.15 1377.95,2334.65 1377.95,2692.91 1496.06,2811.02 1637.8,2811.02 1665.35,2838.58 1665.35,2992.13 1724.41,3051.18 1751.97,3051.18 1917.32,3216.54 1937.01,3216.54 1964.57,3244.09 1964.57,3318.11 J19.10@2014.17,3367.72
  L6 w5.4: v2(1405.51,1988.19) R43.2@1405.51,2015.75
CPU_GPIO0_R: J2.13 R42.1 R43.1 | length 497
  L1 w5.4: J2.13@922.83,1925.2 944.88,1925.2 952.76,1933.07 1019.69,1933.07 1045.08,1958.46 1322.38,1958.46 1352.11,1988.19 v2(1366.14,1988.19)
  L6 w5.4: v2(1366.14,1988.19) R42.1@1366.14,2015.75
CPU_GPIO1: J2.15 J19.11 | length 2370.7
  L1 w5.4: J2.15@922.83,1909.45 956.69,1909.45 964.57,1917.32 1043.31,1917.32 1059.06,1933.07 1444.88,1933.07 v2(1480.32,1968.5)
  L3 w5.9: v2(1480.32,1968.5) 1480.32,2082.68 1448.82,2114.17 1448.82,2303.15 1413.39,2338.58 1413.39,2685.04 1507.87,2779.53 1708.66,2779.53 1763.78,2834.65 1763.78,2996.06 1972.44,3204.72 2064.57,3204.72 2114.17,3254.33 J19.11@2114.17,3267.72
CPU_GPIO2: J3.50 J18.5 | length 1049.2
  L1 w5.4: J3.50@1295.28,2273.23 1295.28,2295.28 1362.2,2362.2 1449.1,2362.2 1539.65,2452.76 1539.65,2629.64 1507.87,2661.42 v2(1507.87,2708.66)
  L6 w5.4: v2(1507.87,2708.66) 1606.3,2807.09 1637.8,2807.09 1665.35,2834.65 1665.35,2893.7 1692.91,2921.26 1766.93,2921.26 J18.5@1814.17,2874.02
CPU_GPIO3: J3.56 J18.6 | length 1204.5
  L1 w5.4: J3.56@1248.03,2273.23 1248.03,2350.39 1342.52,2444.88 1434.78,2444.88 1480.32,2490.41 1480.32,2582.68 1460.63,2602.36 v2(1460.63,2625.98)
  L6 w5.4: v2(1460.63,2625.98) 1460.63,2716.54 1562.99,2818.9 1562.99,2992.13 1594.49,3023.62 1764.57,3023.62 J18.6@1814.17,2974.02
CPU_GPIO4: J3.60 J18.7 | length 1048.2
  L1 w5.4: J3.60@1216.54,2273.23 1216.54,2358.27 v2(1283.46,2425.2)
  L6 w5.4: v2(1283.46,2425.2) 1350.39,2425.2 1381.89,2456.69 1381.89,2519.69 1496.06,2633.86 1496.06,2659.39 1590.81,2754.13 1794.29,2754.13 J18.7@1914.17,2874.02
CPU_GPIO5: J3.62 J18.8 | length 1342.1
  L1 w5.4: J3.62@1200.79,2273.23 1200.79,2377.95 v2(1248.03,2425.2)
  L6 w5.4: v2(1248.03,2425.2) 1271.65,2448.82 1330.71,2448.82 1358.27,2476.38 1358.27,2527.56 1421.26,2590.55 1421.26,2710.89 1535.43,2825.06 1535.43,3011.81 1578.74,3055.12 1833.07,3055.12 J18.8@1914.17,2974.02
CPU_GPIO6: J3.64 J18.9 | length 1225
  L1 w5.4: J3.64@1185.04,2273.23 1185.04,2397.64 v2(1212.6,2425.2)
  L6 w5.4: v2(1212.6,2425.2) 1251.97,2385.83 1354.33,2385.83 1409.45,2440.94 1409.45,2511.81 1517.72,2620.08 1541.67,2620.08 1639.9,2718.31 1816.73,2718.31 1885.83,2787.4 1927.56,2787.4 J18.9@2014.17,2874.02
CPU_GPIO7: J3.66 J18.10 | length 1513.5
  L1 w5.4: J3.66@1169.29,2273.23 v2(1169.29,2425.2)
  L6 w5.4: v2(1169.29,2425.2) 1171,2425.2 1265.49,2519.69 1322.83,2519.69 1397.64,2594.49 1397.64,2720.47 1507.87,2830.71 1507.87,3039.37 1555.12,3086.61 1901.57,3086.61 J18.10@2014.17,2974.02
CSI1_GPIO: J3.19 R34.2 | length 403.8
  L1 w5.4: v2(1354.33,2114.17) 1368.37,2114.17 1389.82,2092.72 1502.17,2092.72 1531.5,2122.05 J3.19@1531.5,2151.97
  L6 w5.4: R34.2@1240.16,2015.75 1240.16,2039.37 1271.65,2070.87 1322.83,2070.87 1354.33,2102.36 v2(1354.33,2114.17)
CSI1_GPIO_R: J12.11 R34.1 | length 2281.6
  L1 w5.4: v1(200.79,1299.21) J12.11@251.97,1299.21
  L3 w5.9: v1(795.28,2122.05) 830.71,2086.61 1145.67,2086.61 v1(1188.98,2043.31)
  L6 w5.4: v1(200.79,1299.21) 228.35,1326.77 228.35,1781.75 316.67,1870.08 377.95,1870.08 413.39,1905.51 413.39,2088.33 440.94,2115.88 440.94,2338.58 501.77,2399.41 692.91,2399.41 722.24,2370.08 722.24,2297.44 748.03,2271.65 748.03,2169.29 v1(795.28,2122.05) ; v1(1188.98,2043.31) 1188.98,2027.56 R34.1@1200.79,2015.75
CSI1_PIXCLK: J3.22 R35.1 | length 557.1
  L1 w5.4: v2(1370.08,2311.02) 1385.83,2326.77 1440.94,2326.77 1464.57,2303.15 1503.94,2303.15 1515.75,2291.34 J3.22@1515.75,2273.23
  L3 w5.9: v2(1370.08,2311.02) 1370.08,2137.8 v2(1393.7,2114.17)
  L6 w5.4: R35.1@1287.4,2015.75 1287.4,2035.43 1303.15,2051.18 1342.52,2051.18 1393.7,2102.36 v2(1393.7,2114.17)
CSI1_PIXCLK_R: J12.12 R35.2 R42.2 | length 2569.7
  L1 w5.4: v1(200.79,1259.84) J12.12@251.97,1259.84
  L3 w5.9: v1(795.28,2157.48) 807.87,2144.88 1154.33,2144.88 1192.13,2107.09 1231.5,2107.09 1326.77,2011.81 v1(1326.77,1988.19)
  L6 w5.4: v1(200.79,1259.84) 166.93,1293.7 166.93,1706.3 188.98,1728.35 188.98,1795.28 295.28,1901.57 326.77,1901.57 371.85,1946.65 371.85,2096.26 413.39,2137.8 413.39,2196.85 389.76,2220.47 389.76,2316.47 512.46,2439.17 686.81,2439.17 775.59,2350.39 775.59,2177.17 v1(795.28,2157.48) ; v1(1326.77,1988.19) R35.2@1326.77,2015.75
CSI_CLK0_N: J2.86 J12.8 | length 1578
  L1 w5.4: v1(185.04,1409.45) 201.77,1409.45 209.64,1417.32 J12.8@251.97,1417.32 ; J2.86@801.57,1358.27 818.31,1358.27 818.39,1358.35 847.33,1358.35 v2(851.18,1362.2)
  L3 w6: v1(185.04,1409.45) 153.54,1409.45 128.58,1384.48 128.58,1119.45 299.21,948.82 377.95,948.82 408.11,978.97 570.4,978.97 806.62,1215.19 877.16,1215.19 902.92,1240.95 902.92,1337.79 880.27,1360.44 852.95,1360.44 v2(851.18,1362.2)
CSI_CLK0_P: J2.88 J12.9 | length 1578.1
  L1 w5.4: v1(185.04,1385.83) 201.77,1385.83 209.64,1377.95 J12.9@251.97,1377.95 ; J2.88@801.57,1342.52 818.31,1342.52 818.39,1342.44 847.32,1342.44 v2(851.18,1338.58)
  L3 w6: v1(185.04,1385.83) 177.27,1385.83 170.74,1392.36 160.62,1392.36 145.67,1377.41 145.67,1342.52 152.86,1335.33 174.96,1335.33 182.83,1327.46 182.83,1311.71 174.96,1303.83 152.82,1303.83 145.67,1296.68 145.67,1126.53 306.29,965.91 370.87,965.91 401.03,996.06 563.32,996.06 799.54,1232.28 870.08,1232.28 885.83,1248.03 885.83,1263.78 878.64,1270.97 858.51,1270.97 850.63,1278.84 850.63,1294.59 858.51,1302.47 878.68,1302.47 885.83,1309.62 885.83,1330.71 873.19,1343.35 855.95,1343.35 v2(851.18,1338.58)
CSI_D0_N: J2.92 J12.2 | length 1574.7
  L1 w5.4: v1(94.49,1559.06) 94.49,1656.2 119.56,1681.26 169.13,1681.26 196.85,1653.54 J12.2@251.97,1653.54 ; v2(767.72,1314.96) 771.57,1311.11 784.76,1311.11 784.84,1311.02 J2.92@801.57,1311.02
  L3 w6: v1(94.49,1559.06) 97.75,1562.32 97.75,1625.86 125.44,1653.54 224.96,1653.54 366.14,1512.36 366.14,1169.29 388.59,1146.84 485.42,1146.84 573.46,1234.88 573.46,1290.54 594.61,1311.69 764.45,1311.69 v2(767.72,1314.96)
CSI_D0_P: J2.94 J12.3 | length 1574.9
  L1 w5.4: v1(118.11,1559.06) 118.11,1566.28 110.4,1573.99 110.4,1590.55 125.98,1606.14 125.98,1618.62 110.4,1634.21 110.4,1649.61 126.15,1665.35 162.54,1665.35 213.72,1614.17 J12.3@251.97,1614.17 ; v2(767.72,1291.34) 771.57,1295.2 784.76,1295.2 784.84,1295.28 J2.94@801.57,1295.28
  L3 w6: v1(118.11,1559.06) 114.84,1562.32 114.84,1618.78 132.52,1636.45 145.67,1636.45 152.82,1629.3 152.82,1620.94 160.69,1613.07 176.44,1613.07 184.32,1620.94 184.32,1629.26 191.51,1636.45 217.88,1636.45 349.05,1505.28 349.05,1162.21 381.51,1129.75 492.5,1129.75 590.55,1227.8 590.55,1283.46 601.69,1294.6 764.45,1294.6 v2(767.72,1291.34)
CSI_D1_N: J2.98 J12.5 | length 1575.7
  L1 w5.4: v1(94.49,1409.45) 94.49,1514.63 115.3,1535.43 J12.5@251.97,1535.43 ; v2(736.22,1267.72) 740.08,1263.86 784.76,1263.86 784.84,1263.78 J2.98@801.57,1263.78
  L3 w6: v1(94.49,1409.45) 97.75,1412.71 97.75,1503.81 129.37,1535.43 213.15,1535.43 267.72,1480.86 267.72,1114.17 299.79,1082.1 527.1,1082.1 594.61,1149.61 612.8,1149.61 629.92,1166.73 629.92,1184.92 709.46,1264.45 732.95,1264.45 v2(736.22,1267.72)
CSI_D1_P: J2.100 J12.6 | length 1575.9
  L1 w5.4: v1(118.11,1409.45) 118.11,1416.68 110.4,1424.39 110.4,1436.5 125.98,1452.08 125.98,1464.57 110.4,1480.15 110.4,1508.04 121.89,1519.52 186.18,1519.52 209.64,1496.06 J12.6@251.97,1496.06 ; v2(736.22,1244.09) 740.08,1247.95 784.76,1247.95 784.84,1248.03 J2.100@801.57,1248.03
  L3 w6: v1(118.11,1409.45) 114.84,1412.71 114.84,1433.07 122,1440.22 130.35,1440.22 138.23,1448.1 138.23,1463.84 130.35,1471.72 122.03,1471.72 114.84,1478.91 114.84,1496.73 136.45,1518.34 206.07,1518.34 250.63,1473.78 250.63,1107.09 292.71,1065.01 534.18,1065.01 601.69,1132.52 619.88,1132.52 647.01,1159.65 647.01,1177.84 716.54,1247.36 732.95,1247.36 v2(736.22,1244.09)
CSPI1_CLK: J2.23 U8.6 | length 1750.1
  L1 w5.4: J2.23@922.83,1846.46 960.63,1846.46 968.5,1854.33 1681.1,1854.33 1708.66,1826.77 1728.35,1826.77 1744.09,1842.52 v2(1744.09,1866.14) ; U8.6@1812.99,2600.98 v2(1846.46,2600.98)
  L3 w5.9: v2(1744.09,1866.14) 1744.09,2007.87 1759.84,2023.62 1759.84,2156.65 1885.83,2282.63 1885.83,2437.01 1858.27,2464.57 1858.27,2515.75 1889.76,2547.24 1889.76,2582.68 1871.46,2600.98 v2(1846.46,2600.98)
CSPI1_CS0: J2.29 U8.1 | length 1717.8
  L1 w5.4: J2.29@922.83,1799.21 1074.8,1799.21 1084.9,1789.11 1177.17,1789.11 1190.69,1775.59 1622.05,1775.59 v2(1629.92,1783.46) ; v2(1562.99,2700.98) U8.1@1596.46,2700.98
  L3 w5.9: v2(1562.99,2700.98) 1540.16,2678.15 1540.16,2299.26 1559.06,2280.36 1559.06,2236.22 1574.8,2220.47 1574.8,2170.91 1629.92,2115.79 v2(1629.92,1783.46)
CSPI1_MISO: J2.27 U8.2 | length 1744.3
  L1 w5.4: J2.27@922.83,1814.96 1177.17,1814.96 1190.75,1801.38 1651.38,1801.38 v2(1669.29,1783.46) ; v2(1562.99,2666.73) 1578.74,2650.98 U8.2@1596.46,2650.98
  L3 w5.9: v2(1562.99,2666.73) 1594.49,2635.24 1594.49,2480.31 1578.74,2464.57 1578.74,2318.9 1618.11,2279.53 1618.11,2212.6 1669.29,2161.42 v2(1669.29,1783.46) v2@1672.44,1786.61
CSPI1_MOSI: J2.25 U8.5 | length 1722.8
  L1 w5.4: J2.25@922.83,1830.71 1188.98,1830.71 1196.85,1822.83 1677.17,1822.83 v2(1716.54,1783.46) ; U8.5@1812.99,2550.98 v2(1846.46,2550.98)
  L3 w5.9: v2(1716.54,1783.46) 1708.66,1791.34 1708.66,2188.98 1861.37,2341.69 1861.37,2406.35 1803.15,2464.57 1803.15,2507.68 v2(1846.46,2550.98)
CSPI2_CLK: J3.70 J17.1 | length 2343.6
  L1 w5.4: J17.1@551.18,3267.72 602.36,3318.9 602.36,3413.39 661.42,3472.44 1240.16,3472.44 1311.02,3401.57 1311.02,3244.09 1342.52,3212.6 1342.52,3035.43 1287.4,2980.31 1287.4,2795.28 1228.35,2736.22 1055.12,2736.22 1033.27,2714.37 1033.27,2506.1 1137.8,2401.57 J3.70@1137.8,2273.23
CSPI2_CS0: J3.76 J17.5 | length 1666
  L1 w5.4: J17.5@751.18,3267.72 751.18,3233.07 789.57,3194.69 1175.39,3194.69 1228.35,3141.73 1228.35,3074.8 1181.1,3027.56 1122.05,3027.56 1102.36,3007.87 1102.36,2850.39 1074.8,2822.83 1019.69,2822.83 940.94,2744.09 940.94,2472.44 1090.55,2322.83 J3.76@1090.55,2273.23
CSPI2_CS1: J3.78 J17.6 | length 1805.9
  L1 w5.4: J17.6@751.18,3367.72 751.18,3341.73 700.79,3291.34 700.79,3236.22 767.72,3169.29 1161.42,3169.29 1200.79,3129.92 1200.79,3086.61 1165.35,3051.18 1051.18,3051.18 1000,3000 1000,2838.58 913.39,2751.97 913.39,2468.5 1074.8,2307.09 J3.78@1074.8,2273.23
CSPI2_MISO: J3.74 J17.3 | length 2071.8
  L1 w5.4: J17.3@651.18,3267.72 651.18,3292.91 700.79,3342.52 700.79,3397.64 724.41,3421.26 1177.17,3421.26 1216.54,3381.89 1216.54,3212.6 1259.84,3169.29 1259.84,3059.06 1204.72,3003.94 1204.72,2834.65 1165.35,2795.28 1031.5,2795.28 972.44,2736.22 972.44,2476.38 1106.3,2342.52 J3.74@1106.3,2273.23
CSPI2_MOSI: J3.72 J17.4 | length 2074.6
  L1 w5.4: J17.4@651.18,3367.72 651.18,3407.09 688.98,3444.88 1196.85,3444.88 1248.03,3393.7 1248.03,3232.28 1299.21,3181.1 1299.21,3055.12 1236.22,2992.13 1236.22,2811.02 1192.91,2767.72 1047.24,2767.72 1000,2720.47 1000,2488.19 1122.05,2366.14 J3.72@1122.05,2273.23
EN_2V5: R31.2 U11.5 | length 188.6
  L1 w5.4: U11.5@1282.48,2677.17 1282.48,2711.61 1303.15,2732.28 1377.95,2732.28 R31.2@1413.39,2696.85
EN_3V3: R30.2 R220.2 U10.12 | length 2707.4
  L1 w5.4: R220.2@1413.39,2562.99 1413.39,2551.18 1429.13,2535.43 R30.2@1429.13,2511.81 1444.88,2496.06 v2(1460.63,2496.06) ; U10.12@2148.62,901.57 2160.43,901.57 2204.72,945.87 v1(2204.72,952.76)
  L3 w5.9: v1(1992.13,2515.75) 2059.06,2448.82 2059.06,2078.74 1921.26,1940.94 1921.26,1795.28 1858.27,1732.28 1858.27,1689.81 1917.37,1630.71 1940.99,1630.71 1968.55,1603.15 1983.46,1603.15 2252.76,1333.86 2252.76,1075.59 2224.41,1047.24 2224.41,972.44 v1(2204.72,952.76)
  L6 w5.4: v2(1460.63,2496.06) 1496.06,2496.06 1649.61,2649.61 1826.77,2649.61 1960.63,2515.75 v1(1992.13,2515.75)
EN_5V: R27.1 U9.12 | length 202.9
  L1 w5.4: R27.1@1586.61,350.39 1604.13,367.91 1625.53,367.91 1639.51,381.89 1669.29,381.89 1716.54,429.13 U9.12@1756.89,429.13
ENET_LED_LINK: J3.14 J5.11 | length 3202.7
  L1 w5.4: v2(1578.74,2247.24) J3.14@1578.74,2273.23
  L3 w5.9: v2(2208.66,1653.54) 2141.73,1720.47 2141.73,1862.2 2283.46,2003.94 2283.46,2405.51 v2(2366.14,2488.19)
  L6 w5.4: v2(1578.74,2247.24) 1580.91,2249.41 1580.91,2454.92 1665.35,2539.37 1783.46,2539.37 1850.39,2472.44 2015.75,2472.44 2078.74,2535.43 2078.74,2657.48 2141.73,2720.47 2279.53,2720.47 2338.58,2661.42 2338.58,2515.75 v2(2366.14,2488.19) ; v2(2208.66,1653.54) 2311.02,1551.18 2633.86,1551.18 2732.28,1649.61 2732.28,1770.08 J5.11@2674.41,1827.95
ENET_LED_RX: J3.16 J5.9 | length 1957.7
  L1 w5.4: J3.16@1562.99,2273.23 v2(1562.99,2303.15)
  L6 w5.4: v2(1562.99,2303.15) 1539.37,2326.77 1539.37,2472.44 1649.61,2582.68 1787.4,2582.68 1876.18,2493.9 2009.65,2493.9 2055.12,2539.37 2055.12,2673.23 2122.05,2740.16 2299.21,2740.16 2362.2,2677.17 2362.2,2543.31 2456.69,2448.82 2641.73,2448.82 2674.41,2416.14 J5.9@2674.41,2277.95
FB_2V5: R225.1 R226.2 U11.8 | length 195.1
  L1 w11.02: 1133.86,2637.8 U11.8@1166.34,2637.8
  L1 w15.75: R225.1@1090.55,2515.75 1082.68,2523.62 R226.2@1082.68,2614.17 1102.36,2614.17 1125.98,2637.8 1133.86,2637.8
FB_3V3: R216.1 R217.2 U10.3 | length 177.1
  L1 w9.06: 1996.06,905.51 2003.94,905.51 2007.87,901.57 U10.3@2032.48,901.57
  L1 w13.78: R217.2@1885.83,952.76 1905.51,933.07 1937.01,933.07 1948.82,921.26 R216.1@1948.82,905.51 1996.06,905.51
FB_5V: R211.1 R213.2 U9.3 | length 149.1
  L1 w9.06: U9.3@1873.03,429.13 1889.76,429.13 1909.45,409.45
  L1 w15.75: 1909.45,409.45 1917.32,401.57 R211.1@1940.94,401.57 1940.94,385.83 1976.38,350.39 R213.2@1980.32,350.39
FB_+1V5: R18.1 R20.2 U6.8 | length 124.7
  L1 w11.02: 413.39,1830.71 U6.8@413.39,1863.19
  L1 w15.75: R20.2@370.08,1787.4 R18.1@417.32,1787.4 417.32,1811.02 413.39,1814.96 413.39,1830.71
FB_+1V8: R82.1 R83.2 U2.8 | length 162.3
  L1 w11.02: U2.8@1042.32,267.72 1078.74,267.72
  L1 w15.75: 1078.74,267.72 1118.11,267.72 R83.2@1129.92,279.53 1129.92,295.28 1165.35,330.71 R82.1@1165.35,334.65
FLEXCAN1_RX: J2.32 J17.8 | length 1881.3
  L1 w5.4: J2.32@801.57,1783.46 771.65,1783.46 681.1,1874.02 681.1,1929.13 637.8,1972.44 637.8,2102.36 685.04,2149.61 685.04,2220.47 v1(826.77,2362.2)
  L3 w5.9: v1(826.77,2362.2) 988.19,2523.62 988.19,2681.1 1000,2692.91 1000,3027.56 v2(952.76,3074.8)
  L6 w5.4: J17.8@851.18,3367.72 901.57,3317.32 901.57,3125.98 v2(952.76,3074.8)
FLEXCAN1_TX: J2.30 J17.9 | length 1811.1
  L1 w5.4: J2.30@801.57,1799.21 775.59,1799.21 700.79,1874.02 700.79,1937.01 657.48,1980.31 657.48,2086.61 712.6,2141.73 712.6,2208.66 v1(826.77,2322.83)
  L3 w5.9: v1(826.77,2322.83) 1031.5,2527.56 1031.5,2653.54 1102.36,2724.41 1102.36,3007.87 1086.61,3023.62 1051.18,3023.62 v2(1000,3074.8)
  L6 w5.4: J17.9@951.18,3267.72 951.18,3139.37 1000,3090.55 v2(1000,3074.8)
